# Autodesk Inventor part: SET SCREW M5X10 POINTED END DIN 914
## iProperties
Created: 2006-02
Part Number: SET SCREW M5X10 POINTED END DIN 914
Material: Steel, Mild
Description: Hexagon Socket Set Screw
Document SubType Name: Modeling
Standard: DIN 914
Designer: Andy Moles
Standards Organization: DIN
Language: en-US
Size Designation: M5 x 10
Categories: <MemberInstance><Categories><Category DisplayName="Fasteners" InternalName="e4da775c-781d-43d5-af7c-5136215cf5a6" Mnemonic="FSTN"><Category DisplayName="Bolts"
Density: 7.86 g/cm^3
Mass: 1.13067 g
Surface Area: 1.87837 cm^2
Volume: 0.143851 cm^3
Author: Andy Moles
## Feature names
1. Body [Revolution]
2. Slot [Extrusion]
3. Chamfer1
4. Chamfer2
